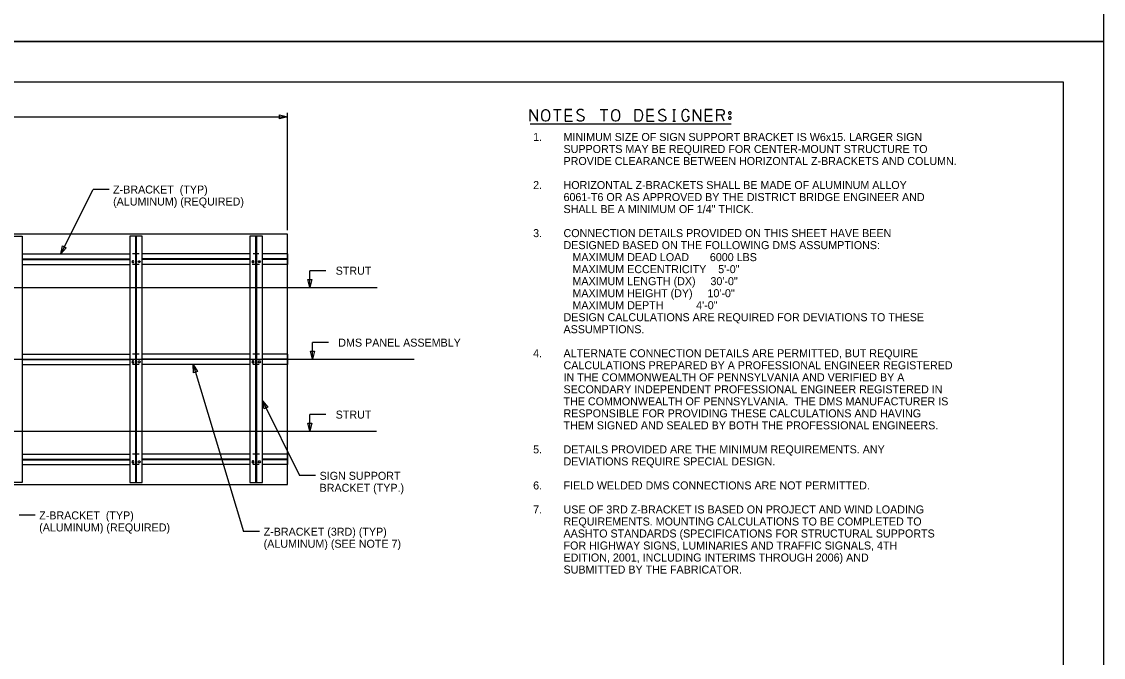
# Model space of a CAD drawing. Extents: x 3829340 to 3831660, y 499389 to 501171.
# Drawn here: x 3830616.6 to 3831022, y 499752.6 to 499990.7 of the extents above; entities that cross this region are included whole.
import ezdxf

# ---------------------------------------------------------------- set-up
doc = ezdxf.new("R2010")
doc.units = 0
for name, color, linetype in [('0-ANCHOR', 7, 'Continuous'), ('2', 7, 'Continuous'), ('CNTR', 7, 'Continuous'), ('DIM TXT', 7, 'Continuous'), ('PLT-BNDY', 7, 'Continuous'), ('sign', 7, 'Continuous'), ('structure', 7, 'Continuous')]:
    doc.layers.add(name, color=color, linetype=linetype)

msp = doc.modelspace()

# ---------------------------------------------------------------- linework, layer by layer
at = {"layer": '0-ANCHOR'}
for p, q in [((3830658.11, 499901.15), (3830657.9, 499900.79)), ((3830658.53, 499901.15), (3830658.11, 499901.15)), ((3830658.73, 499900.79), (3830658.53, 499901.15)), ((3830660.24, 499900.79), (3830660.45, 499901.15)), ((3830660.45, 499901.15), (3830660.86, 499901.15)), ((3830660.86, 499901.15), (3830661.07, 499900.79)), ((3830703.11, 499901.15), (3830702.9, 499900.79)), ((3830703.53, 499901.15), (3830703.11, 499901.15)), ((3830703.73, 499900.79), (3830703.53, 499901.15)), ((3830705.24, 499900.79), (3830705.45, 499901.15)), ((3830705.45, 499901.15), (3830705.86, 499901.15)), ((3830705.86, 499901.15), (3830706.07, 499900.79)), ((3830657.9, 499900.79), (3830658.11, 499900.43)), ((3830658.11, 499900.43), (3830658.53, 499900.43)), ((3830658.53, 499900.43), (3830658.73, 499900.79)), ((3830660.45, 499900.43), (3830660.24, 499900.79)), ((3830660.86, 499900.43), (3830660.45, 499900.43)), ((3830661.07, 499900.79), (3830660.86, 499900.43)), ((3830702.9, 499900.79), (3830703.11, 499900.43)), ((3830703.11, 499900.43), (3830703.53, 499900.43)), ((3830703.53, 499900.43), (3830703.73, 499900.79)), ((3830705.45, 499900.43), (3830705.24, 499900.79)), ((3830705.86, 499900.43), (3830705.45, 499900.43)), ((3830706.07, 499900.79), (3830705.86, 499900.43)), ((3830658.11, 499863.65), (3830657.9, 499863.29)), ((3830657.9, 499863.29), (3830658.11, 499862.93)), ((3830658.53, 499863.65), (3830658.11, 499863.65)), ((3830658.11, 499862.93), (3830658.53, 499862.93)), ((3830658.73, 499863.29), (3830658.53, 499863.65)), ((3830658.53, 499862.93), (3830658.73, 499863.29)), ((3830660.24, 499863.29), (3830660.45, 499863.65)), ((3830660.45, 499862.93), (3830660.24, 499863.29)), ((3830660.45, 499863.65), (3830660.86, 499863.65)), ((3830660.86, 499862.93), (3830660.45, 499862.93)), ((3830660.86, 499863.65), (3830661.07, 499863.29)), ((3830661.07, 499863.29), (3830660.86, 499862.93)), ((3830703.11, 499863.65), (3830702.9, 499863.29)), ((3830702.9, 499863.29), (3830703.11, 499862.93)), ((3830703.53, 499863.65), (3830703.11, 499863.65)), ((3830703.11, 499862.93), (3830703.53, 499862.93)), ((3830703.73, 499863.29), (3830703.53, 499863.65)), ((3830703.53, 499862.93), (3830703.73, 499863.29)), ((3830705.24, 499863.29), (3830705.45, 499863.65)), ((3830705.45, 499862.93), (3830705.24, 499863.29)), ((3830705.45, 499863.65), (3830705.86, 499863.65)), ((3830705.86, 499862.93), (3830705.45, 499862.93)), ((3830705.86, 499863.65), (3830706.07, 499863.29)), ((3830706.07, 499863.29), (3830705.86, 499862.93)), ((3830658.11, 499826.15), (3830657.9, 499825.79)), ((3830657.9, 499825.79), (3830658.11, 499825.43)), ((3830658.53, 499826.15), (3830658.11, 499826.15)), ((3830658.11, 499825.43), (3830658.53, 499825.43)), ((3830658.73, 499825.79), (3830658.53, 499826.15)), ((3830658.53, 499825.43), (3830658.73, 499825.79)), ((3830660.24, 499825.79), (3830660.45, 499826.15)), ((3830660.45, 499825.43), (3830660.24, 499825.79)), ((3830660.45, 499826.15), (3830660.86, 499826.15)), ((3830660.86, 499825.43), (3830660.45, 499825.43)), ((3830660.86, 499826.15), (3830661.07, 499825.79)), ((3830661.07, 499825.79), (3830660.86, 499825.43)), ((3830703.11, 499826.15), (3830702.9, 499825.79)), ((3830702.9, 499825.79), (3830703.11, 499825.43)), ((3830703.53, 499826.15), (3830703.11, 499826.15)), ((3830703.11, 499825.43), (3830703.53, 499825.43)), ((3830703.73, 499825.79), (3830703.53, 499826.15)), ((3830703.53, 499825.43), (3830703.73, 499825.79)), ((3830705.24, 499825.79), (3830705.45, 499826.15)), ((3830705.45, 499825.43), (3830705.24, 499825.79)), ((3830705.45, 499826.15), (3830705.86, 499826.15)), ((3830705.86, 499825.43), (3830705.45, 499825.43)), ((3830705.86, 499826.15), (3830706.07, 499825.79)), ((3830706.07, 499825.79), (3830705.86, 499825.43))]:
    msp.add_line(p, q, dxfattribs=at)
at = {"layer": '2'}
for p, q in [((3830220.96, 499968.19), (3831006.96, 499968.19)), ((3831006.96, 499968.19), (3831006.96, 499404.19))]:
    msp.add_line(p, q, dxfattribs=at)
at = {"layer": 'CNTR'}
for p, q in [((3830463.09, 499891.17), (3830749.83, 499891.17)), ((3830463.09, 499864.22), (3830763.65, 499864.22)), ((3830463.09, 499837.27), (3830749.59, 499837.27))]:
    msp.add_line(p, q, dxfattribs=at)
at = {"layer": 'DIM TXT'}
for p, q in [((3830815.93, 499957.74), (3830818.82, 499957.74)), ((3830817.38, 499953.36), (3830817.38, 499957.74)), ((3830817.38, 499953.36), (3830817.38, 499957.74)), ((3830820.31, 499957.74), (3830822.82, 499957.74)), ((3830833.43, 499957.74), (3830836.32, 499957.74)), ((3830834.88, 499953.36), (3830834.88, 499957.74)), ((3830834.88, 499953.36), (3830834.88, 499957.74)), ((3830850.93, 499957.74), (3830853.45, 499957.74)), ((3830860.64, 499957.74), (3830861.68, 499957.74)), ((3830861.16, 499953.36), (3830861.16, 499957.74)), ((3830872.8, 499957.74), (3830875.32, 499957.74)), ((3830467.77, 499955.06), (3830716.2, 499955.06)), ((3830716.2, 499912.59), (3830716.2, 499956.56)), ((3830820.31, 499955.57), (3830822.82, 499955.57)), ((3830820.31, 499955.57), (3830822.82, 499955.57)), ((3830850.93, 499955.57), (3830853.45, 499955.57)), ((3830850.93, 499955.57), (3830853.45, 499955.57)), ((3830872.8, 499955.57), (3830875.32, 499955.57)), ((3830872.8, 499955.57), (3830875.32, 499955.57)), ((3830879.9, 499953.36), (3830878.9, 499955.6)), ((3830807.18, 499952.36), (3830882.48, 499952.36)), ((3830860.64, 499953.36), (3830861.68, 499953.36)), ((3830631.29, 499903.67), (3830643.4, 499927.88)), ((3830649.4, 499927.88), (3830643.4, 499927.88)), ((3830724.59, 499891.17), (3830724.59, 499897.42)), ((3830730.59, 499897.42), (3830724.59, 499897.42)), ((3830725.57, 499864.22), (3830725.57, 499870.47)), ((3830731.57, 499870.47), (3830725.57, 499870.47)), ((3830680.9, 499862.27), (3830699.81, 499799.72)), ((3830706.83, 499848.71), (3830720.78, 499820.66)), ((3830724.59, 499837.27), (3830724.59, 499843.52)), ((3830730.59, 499843.52), (3830724.59, 499843.52)), ((3830726.78, 499820.66), (3830720.78, 499820.66)), ((3830621.71, 499805.83), (3830615.71, 499805.83)), ((3830705.81, 499799.72), (3830699.81, 499799.72))]:
    msp.add_line(p, q, dxfattribs=at)
for points in [[(3830807.18, 499953.36), (3830807.18, 499957.74), (3830809.9, 499953.36), (3830809.9, 499957.74)], [(3830812.8, 499957.74), (3830813.14, 499957.74), (3830813.73, 499957.5), (3830814.28, 499956.77), (3830814.42, 499955.91), (3830814.42, 499955.12), (3830814.28, 499954.26), (3830813.69, 499953.54), (3830813.14, 499953.36), (3830812.8, 499953.36), (3830812.28, 499953.54), (3830811.69, 499954.26), (3830811.56, 499955.12), (3830811.56, 499955.91), (3830811.69, 499956.81), (3830812.28, 499957.53), (3830812.8, 499957.74)], [(3830822.82, 499957.74), (3830820.31, 499957.74), (3830820.31, 499953.36), (3830822.99, 499953.36)], [(3830827.2, 499957.43), (3830826.51, 499957.74), (3830825.71, 499957.74), (3830824.99, 499957.43), (3830824.68, 499956.88), (3830824.68, 499956.67), (3830825.03, 499956.15), (3830827.02, 499955.12), (3830827.37, 499954.64), (3830827.33, 499954.23), (3830827.02, 499953.67), (3830826.44, 499953.36), (3830825.61, 499953.36), (3830825.23, 499953.5), (3830824.68, 499953.88)], [(3830839.05, 499957.74), (3830839.39, 499957.74), (3830839.98, 499957.5), (3830840.53, 499956.77), (3830840.67, 499955.91), (3830840.67, 499955.12), (3830840.53, 499954.26), (3830839.94, 499953.54), (3830839.39, 499953.36), (3830839.05, 499953.36), (3830838.53, 499953.54), (3830837.94, 499954.26), (3830837.81, 499955.12), (3830837.81, 499955.91), (3830837.94, 499956.81), (3830838.53, 499957.53), (3830839.05, 499957.74)], [(3830846.56, 499957.74), (3830848.14, 499957.74), (3830848.73, 499957.43), (3830849.1, 499956.67), (3830849.28, 499955.67), (3830849.07, 499954.43), (3830848.69, 499953.67), (3830848.14, 499953.36), (3830846.56, 499953.36), (3830846.56, 499957.74)], [(3830853.45, 499957.74), (3830850.93, 499957.74), (3830850.93, 499953.36), (3830853.62, 499953.36)], [(3830857.82, 499957.43), (3830857.13, 499957.74), (3830856.34, 499957.74), (3830855.62, 499957.43), (3830855.31, 499956.88), (3830855.31, 499956.67), (3830855.65, 499956.15), (3830857.65, 499955.12), (3830857.99, 499954.64), (3830857.96, 499954.23), (3830857.65, 499953.67), (3830857.06, 499953.36), (3830856.24, 499953.36), (3830855.86, 499953.5), (3830855.31, 499953.88)], [(3830866.78, 499956.88), (3830866.19, 499957.6), (3830865.64, 499957.74), (3830865.23, 499957.74), (3830864.78, 499957.6), (3830864.19, 499956.88), (3830864.06, 499955.95), (3830864.06, 499955.22), (3830864.23, 499954.19), (3830864.74, 499953.5), (3830865.26, 499953.36), (3830865.64, 499953.36), (3830866.19, 499953.5), (3830866.78, 499954.23), (3830866.78, 499955.09), (3830866.02, 499955.09)], [(3830868.43, 499953.36), (3830868.43, 499957.74), (3830871.15, 499953.36), (3830871.15, 499957.74)], [(3830875.32, 499957.74), (3830872.8, 499957.74), (3830872.8, 499953.36), (3830875.49, 499953.36)], [(3830877.18, 499953.36), (3830877.18, 499957.74), (3830878.94, 499957.74), (3830879.45, 499957.57), (3830879.9, 499956.88), (3830879.9, 499956.46), (3830879.49, 499955.78), (3830878.94, 499955.6), (3830877.18, 499955.6)], [(3830882.48, 499956.4), (3830882.48, 499956.53), (3830882.45, 499956.67), (3830882.38, 499956.77), (3830882.24, 499956.88), (3830882.11, 499956.95), (3830881.9, 499956.95), (3830881.76, 499956.88), (3830881.62, 499956.74), (3830881.55, 499956.6), (3830881.55, 499956.4), (3830881.62, 499956.22), (3830881.76, 499956.09), (3830881.93, 499956.02), (3830882.11, 499956.02), (3830882.28, 499956.09), (3830882.42, 499956.22), (3830882.48, 499956.4)], [(3830882.48, 499954.5), (3830882.48, 499954.64), (3830882.45, 499954.78), (3830882.38, 499954.88), (3830882.24, 499954.98), (3830882.11, 499955.05), (3830881.9, 499955.05), (3830881.76, 499954.98), (3830881.62, 499954.85), (3830881.55, 499954.71), (3830881.55, 499954.5), (3830881.62, 499954.33), (3830881.76, 499954.19), (3830881.93, 499954.12), (3830882.11, 499954.12), (3830882.28, 499954.19), (3830882.42, 499954.33), (3830882.48, 499954.5)]]:
    msp.add_lwpolyline(points, dxfattribs=at)
for points in [[(3830713.2, 499955.81), (3830716.2, 499955.06), (3830713.2, 499954.31)], [(3830633.3, 499906.02), (3830631.29, 499903.67), (3830631.96, 499906.69)], [(3830725.34, 499894.17), (3830724.59, 499891.17), (3830723.84, 499894.17)], [(3830726.32, 499867.22), (3830725.57, 499864.22), (3830724.82, 499867.22)], [(3830681.05, 499859.18), (3830680.9, 499862.27), (3830682.48, 499859.61)], [(3830707.49, 499845.69), (3830706.83, 499848.71), (3830708.83, 499846.36)], [(3830725.34, 499840.27), (3830724.59, 499837.27), (3830723.84, 499840.27)]]:
    msp.add_lwpolyline(points, close=True, dxfattribs=at)
at = {"layer": 'PLT-BNDY'}
for points in [[(3830180.96, 500577.19), (3831021.96, 500577.19), (3831021.96, 499983.19), (3830180.96, 499983.19)], [(3830180.96, 499983.19), (3831021.96, 499983.19), (3831021.96, 499389.19), (3830180.96, 499389.19)]]:
    msp.add_lwpolyline(points, close=True, dxfattribs=at)
at = {"layer": 'sign'}
for p, q in [((3830716.2, 499911.09), (3830467.77, 499911.09)), ((3830716.2, 499817.35), (3830716.2, 499911.09)), ((3830616.83, 499903.67), (3830657.15, 499903.67)), ((3830616.83, 499901.82), (3830657.15, 499901.82)), ((3830616.83, 499901.62), (3830657.15, 499901.62)), ((3830660.72, 499903.67), (3830658.22, 499903.67)), ((3830702.15, 499903.67), (3830661.83, 499903.67)), ((3830702.15, 499901.82), (3830661.83, 499901.82)), ((3830702.15, 499901.62), (3830661.83, 499901.62)), ((3830705.49, 499903.67), (3830703.43, 499903.67)), ((3830716.2, 499903.67), (3830706.83, 499903.67)), ((3830716.2, 499901.82), (3830706.83, 499901.82)), ((3830716.2, 499901.62), (3830706.83, 499901.62)), ((3830716.2, 499903.67), (3830716.2, 499899.77)), ((3830616.83, 499899.77), (3830657.15, 499899.77)), ((3830660.61, 499899.77), (3830658.22, 499899.77)), ((3830702.15, 499899.77), (3830661.83, 499899.77)), ((3830705.71, 499899.77), (3830703, 499899.77)), ((3830716.2, 499899.77), (3830706.83, 499899.77)), ((3830616.83, 499866.17), (3830657.15, 499866.17)), ((3830660.72, 499866.17), (3830658.22, 499866.17)), ((3830702.15, 499866.17), (3830661.83, 499866.17)), ((3830705.72, 499866.17), (3830703.22, 499866.17)), ((3830716.2, 499866.17), (3830706.83, 499866.17)), ((3830716.2, 499866.17), (3830716.2, 499862.27)), ((3830616.83, 499864.32), (3830657.15, 499864.32)), ((3830616.83, 499864.12), (3830657.15, 499864.12)), ((3830616.83, 499862.27), (3830657.15, 499862.27)), ((3830660.61, 499862.27), (3830658.22, 499862.27)), ((3830702.15, 499864.32), (3830661.83, 499864.32)), ((3830702.15, 499864.12), (3830661.83, 499864.12)), ((3830702.15, 499862.27), (3830661.83, 499862.27)), ((3830705.61, 499862.27), (3830703.22, 499862.27)), ((3830716.2, 499864.32), (3830706.83, 499864.32)), ((3830716.2, 499864.12), (3830706.83, 499864.12)), ((3830716.2, 499862.27), (3830706.83, 499862.27)), ((3830616.83, 499828.67), (3830657.15, 499828.67)), ((3830660.72, 499828.67), (3830658.22, 499828.67)), ((3830702.15, 499828.67), (3830661.83, 499828.67)), ((3830705.72, 499828.67), (3830703.22, 499828.67)), ((3830716.2, 499828.67), (3830706.83, 499828.67)), ((3830716.2, 499828.67), (3830716.2, 499824.77)), ((3830616.83, 499826.82), (3830657.15, 499826.82)), ((3830616.83, 499826.62), (3830657.15, 499826.62)), ((3830616.83, 499824.77), (3830657.15, 499824.77)), ((3830660.61, 499824.77), (3830658.22, 499824.77)), ((3830702.15, 499826.82), (3830661.83, 499826.82)), ((3830702.15, 499826.62), (3830661.83, 499826.62)), ((3830702.15, 499824.77), (3830661.83, 499824.77)), ((3830705.61, 499824.77), (3830703.22, 499824.77)), ((3830716.2, 499826.82), (3830706.83, 499826.82)), ((3830716.2, 499826.62), (3830706.83, 499826.62)), ((3830716.2, 499824.77), (3830706.83, 499824.77)), ((3830467.77, 499817.35), (3830716.2, 499817.35))]:
    msp.add_line(p, q, dxfattribs=at)
at = {"layer": 'structure'}
for p, q in [((3830612.15, 499910.31), (3830616.83, 499910.31)), ((3830616.83, 499910.31), (3830616.83, 499818.13)), ((3830661.83, 499910.31), (3830657.15, 499910.31)), ((3830657.15, 499910.31), (3830657.15, 499818.13)), ((3830659.4, 499910.31), (3830659.58, 499910.31)), ((3830659.4, 499818.13), (3830659.4, 499910.31)), ((3830659.58, 499910.31), (3830659.58, 499818.13)), ((3830661.83, 499818.13), (3830661.83, 499910.31)), ((3830706.83, 499910.31), (3830702.15, 499910.31)), ((3830702.15, 499910.31), (3830702.15, 499818.13)), ((3830704.4, 499910.31), (3830704.58, 499910.31)), ((3830704.4, 499818.13), (3830704.4, 499910.31)), ((3830704.58, 499910.31), (3830704.58, 499818.13)), ((3830706.83, 499818.13), (3830706.83, 499910.31)), ((3830616.83, 499818.13), (3830612.15, 499818.13)), ((3830657.15, 499818.13), (3830661.83, 499818.13)), ((3830659.58, 499818.13), (3830659.4, 499818.13)), ((3830702.15, 499818.13), (3830706.83, 499818.13)), ((3830704.58, 499818.13), (3830704.4, 499818.13))]:
    msp.add_line(p, q, dxfattribs=at)

# ---------------------------------------------------------------- texts
at = {"layer": 'DIM TXT'}
for s, height, p in [(' 1.', 3, (3830807.18, 499945.99)), ('MINIMUM SIZE OF SIGN SUPPORT BRACKET IS W6x15. LARGER SIGN ', 2.9999, (3830819.68, 499945.99)), ('SUPPORTS MAY BE REQUIRED FOR CENTER-MOUNT STRUCTURE TO ', 2.9999, (3830819.68, 499941.49)), ('PROVIDE CLEARANCE BETWEEN HORIZONTAL Z-BRACKETS AND COLUMN.', 2.9999, (3830819.68, 499936.99)), ('Z-BRACKET  (TYP)', 2.9999, (3830650.9, 499926.32)), (' 2.', 3, (3830807.18, 499927.99)), ('HORIZONTAL Z-BRACKETS SHALL BE MADE OF ALUMINUM ALLOY ', 2.9999, (3830819.68, 499927.99)), ('6061-T6 OR AS APPROVED BY THE DISTRICT BRIDGE ENGINEER AND', 2.9999, (3830819.68, 499923.49)), ('(ALUMINUM) (REQUIRED)', 2.9999, (3830650.9, 499921.82)), ('SHALL BE A MINIMUM OF 1/4" THICK.', 2.9999, (3830819.68, 499918.99)), (' 3.', 3, (3830807.18, 499909.99)), ('CONNECTION DETAILS PROVIDED ON THIS SHEET HAVE BEEN ', 2.9999, (3830819.68, 499909.99)), ('DESIGNED BASED ON THE FOLLOWING DMS ASSUMPTIONS:', 2.9999, (3830819.68, 499905.49)), ('   MAXIMUM DEAD LOAD       6000 LBS', 2.9999, (3830819.68, 499900.99)), ('  STRUT', 3, (3830732.07, 499895.92)), ('   MAXIMUM ECCENTRICITY    5\'-0"', 2.9999, (3830819.68, 499896.49)), ('   MAXIMUM LENGTH (DX)     30\'-0"', 2.9999, (3830819.68, 499891.99)), ('   MAXIMUM HEIGHT (DY)     10\'-0"', 2.9999, (3830819.68, 499887.49)), ('   MAXIMUM DEPTH           4\'-0"', 2.9999, (3830819.68, 499882.99)), ('DESIGN CALCULATIONS ARE REQUIRED FOR DEVIATIONS TO THESE ', 2.9999, (3830819.68, 499878.49)), ('ASSUMPTIONS.', 2.9999, (3830819.68, 499873.99)), ('  DMS PANEL ASSEMBLY', 2.9999, (3830733.05, 499868.97)), (' 4.', 3, (3830807.18, 499864.99)), ('ALTERNATE CONNECTION DETAILS ARE PERMITTED, BUT REQUIRE ', 2.9999, (3830819.68, 499864.99)), ('CALCULATIONS PREPARED BY A PROFESSIONAL ENGINEER REGISTERED ', 2.9999, (3830819.68, 499860.49)), ('IN THE COMMONWEALTH OF PENNSYLVANIA AND VERIFIED BY A ', 2.9999, (3830819.68, 499855.99)), ('SECONDARY INDEPENDENT PROFESSIONAL ENGINEER REGISTERED IN ', 2.9999, (3830819.68, 499851.49)), ('THE COMMONWEALTH OF PENNSYLVANIA.  THE DMS MANUFACTURER IS ', 2.9999, (3830819.68, 499846.99)), ('  STRUT', 3, (3830732.07, 499842.02)), ('RESPONSIBLE FOR PROVIDING THESE CALCULATIONS AND HAVING ', 2.9999, (3830819.68, 499842.49)), ('THEM SIGNED AND SEALED BY BOTH THE PROFESSIONAL ENGINEERS.', 2.9999, (3830819.68, 499837.99)), (' 5.', 3, (3830807.18, 499828.99)), ('DETAILS PROVIDED ARE THE MINIMUM REQUIREMENTS. ANY ', 2.9999, (3830819.68, 499828.99)), ('DEVIATIONS REQUIRE SPECIAL DESIGN.', 2.9999, (3830819.68, 499824.49)), ('SIGN SUPPORT ', 2.9999, (3830728.28, 499819.1)), ('BRACKET (TYP.)', 2.9999, (3830728.28, 499814.61)), (' 6.', 3, (3830807.18, 499815.49)), ('FIELD WELDED DMS CONNECTIONS ARE NOT PERMITTED.', 2.9999, (3830819.68, 499815.49)), (' 7.', 3, (3830807.18, 499806.49)), ('USE OF 3RD Z-BRACKET IS BASED ON PROJECT AND WIND LOADING ', 2.9999, (3830819.68, 499806.49)), ('Z-BRACKET  (TYP)', 2.9999, (3830623.21, 499804.27)), ('REQUIREMENTS. MOUNTING CALCULATIONS TO BE COMPLETED TO ', 2.9999, (3830819.68, 499801.99)), ('(ALUMINUM) (REQUIRED)', 2.9999, (3830623.21, 499799.77)), ('Z-BRACKET (3RD) (TYP)', 2.9999, (3830707.31, 499798.16)), ('AASHTO STANDARDS (SPECIFICATIONS FOR STRUCTURAL SUPPORTS ', 2.9999, (3830819.68, 499797.49)), ('(ALUMINUM) (SEE NOTE 7)', 2.9999, (3830707.31, 499793.66)), ('FOR HIGHWAY SIGNS, LUMINARIES AND TRAFFIC SIGNALS, 4TH ', 2.9999, (3830819.68, 499792.99)), ('EDITION, 2001, INCLUDING INTERIMS THROUGH 2006) AND ', 2.9999, (3830819.68, 499788.49)), ('SUBMITTED BY THE FABRICATOR. ', 2.9999, (3830819.68, 499783.99))]:
    msp.add_text(s, height=height, dxfattribs=at).set_placement(p)

doc.saveas('drawing.dxf')
